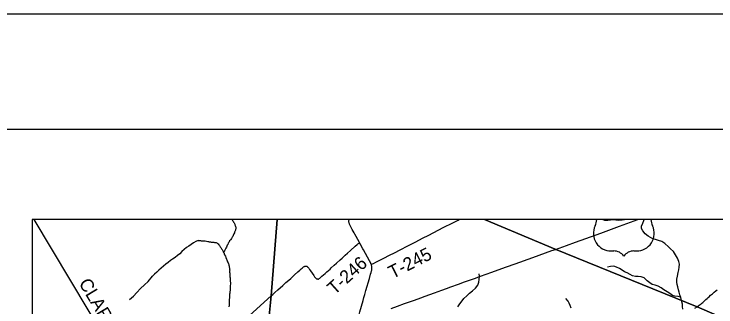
# Model space of a CAD drawing. Extents: x 0 to 34, y 0 to 22.
# Drawn here: x 17.083 to 20.142, y 20.726 to 22 of the extents above; entities that cross this region are included whole.
import ezdxf

# ---------------------------------------------------------------- set-up
doc = ezdxf.new("R2010")
doc.units = 0
for name, color, linetype in [('GM_X_Corporation', 7, 'Continuous'), ('GM_X_County_Road', 7, 'Continuous'), ('GM_X_County_Road_Text', 7, 'Continuous'), ('GM_X_Interstate_Shield', 7, 'Continuous'), ('GM_X_Minor_River', 7, 'Continuous'), ('GM_X_State_Route', 7, 'Continuous'), ('GM_X_Township_Road', 7, 'Continuous'), ('GM_X_Township_Road_Text', 7, 'Continuous'), ('GM_X_US_Location', 7, 'Continuous'), ('GM_X_US_Route', 7, 'Continuous'), ('SH_Border', 7, 'Continuous'), ('SH_Cut_Line', 7, 'Continuous')]:
    doc.layers.add(name, color=color, linetype=linetype)

msp = doc.modelspace()

# ---------------------------------------------------------------- linework, layer by layer
at = {"layer": 'GM_X_Corporation'}
for points in [[(18.23, 21.1059), (17.1625, 21.1059), (17.1625, 14.3059), (17.597, 14.3059), (17.6136, 14.4601), (17.7239, 15.6245), (17.7373, 15.7617), (17.7834, 16.317), (17.8718, 17.2256), (17.9672, 18.2605), (18.0387, 19.0962), (18.0879, 19.5959), (18.1731, 20.4696), (18.203, 20.7746)], [(18.23, 21.1059), (17.1625, 21.1059), (17.1625, 16.0215), (17.412, 16.1394), (17.7834, 16.317), (17.8718, 17.2256), (17.9672, 18.2605), (18.0387, 19.0962), (18.0879, 19.5959), (18.1731, 20.4696), (18.203, 20.7746)], [(17.597, 14.3059), (23.9625, 14.3059), (23.9625, 21.1059), (18.23, 21.1059), (18.203, 20.7746), (18.1731, 20.4696), (18.0879, 19.5959), (18.0387, 19.0962), (17.9672, 18.2605), (17.8718, 17.2256), (17.7834, 16.317), (17.7373, 15.7617), (17.7239, 15.6245), (17.6136, 14.4601)], [(23.8219, 21.1059), (19.1325, 21.1059), (19.4417, 20.9771), (20.0591, 20.7271), (20.5209, 20.5272), (20.9887, 20.3291), (21.1503, 20.1924), (21.2024, 20.1483), (21.462, 19.9289), (21.6862, 19.7442), (22.4736, 19.0897), (22.5453, 19.0171), (22.8523, 19.0143), (22.8728, 18.8666), (23.8372, 18.7818), (23.8567, 18.7798), (23.8401, 19.9225), (23.83, 20.7057)]]:
    msp.add_lwpolyline(points, close=True, dxfattribs=at)
msp.add_lwpolyline([(22.4736, 19.0897), (21.6862, 19.7442), (21.462, 19.9289), (21.2024, 20.1483), (21.1503, 20.1924), (20.9887, 20.3291), (20.5209, 20.5272), (20.0591, 20.7271), (19.4417, 20.9771), (19.1325, 21.1059), (18.23, 21.1059), (18.203, 20.7746), (18.1731, 20.4696), (18.0879, 19.5959), (18.0387, 19.0962), (17.9672, 18.2605), (17.8718, 17.2256), (17.7834, 16.317)], dxfattribs=at)
at = {"layer": 'GM_X_County_Road'}
for points in [[(17.7394, 20.168), (17.6942, 20.2387), (17.6421, 20.3201), (17.1708, 21.1059)], [(18.5889, 21.0055), (18.5868, 21.0092), (18.5809, 21.0199), (18.5738, 21.0327), (18.5684, 21.0424), (18.5652, 21.0481), (18.557, 21.0629), (18.5491, 21.0771), (18.546, 21.0834), (18.5451, 21.0854), (18.5443, 21.0873), (18.5435, 21.09), (18.5429, 21.0923), (18.5424, 21.0946), (18.5422, 21.0969), (18.5423, 21.0988), (18.5425, 21.1017), (18.5431, 21.1045), (18.5435, 21.1059)], [(18.6398, 20.9111), (18.6384, 20.9143), (18.6371, 20.9169), (18.6324, 20.9264), (18.6064, 20.9742), (18.6036, 20.9793), (18.5913, 21.0012), (18.5889, 21.0055)], [(18.5798, 20.665), (18.5829, 20.6767), (18.5834, 20.679), (18.584, 20.6813), (18.5903, 20.7053), (18.6038, 20.7535), (18.6078, 20.7675), (18.6113, 20.7799), (18.6163, 20.797), (18.6315, 20.8499), (18.6368, 20.8685), (18.6388, 20.8756), (18.6405, 20.8824), (18.6415, 20.8864), (18.6422, 20.8899), (18.6425, 20.8931), (18.6427, 20.8959), (18.6426, 20.8981), (18.6424, 20.9009), (18.6419, 20.9039), (18.6413, 20.9067), (18.6405, 20.9092), (18.6398, 20.9111)], [(20.0594, 20.7266), (20.0625, 20.7289), (20.066, 20.7314), (20.0689, 20.7336), (20.0724, 20.7363), (20.0767, 20.7397), (20.0803, 20.7426), (20.0844, 20.746), (20.0876, 20.7489), (20.0931, 20.7539), (20.0976, 20.7579), (20.1026, 20.7625), (20.1071, 20.7665), (20.1117, 20.7707), (20.1184, 20.7766), (20.1264, 20.7836), (20.1337, 20.79), (20.1413, 20.7967), (20.1463, 20.8011)], [(20.0501, 20.7206), (20.0594, 20.7266)]]:
    msp.add_lwpolyline(points, dxfattribs=at)
at = {"layer": 'GM_X_Interstate_Shield'}
for p, q in [((19.8583, 21.1059), (19.622, 21.1059)), ((19.6852, 20.9695), (19.6962, 20.9695)), ((19.7841, 20.9695), (19.7951, 20.9695))]:
    msp.add_line(p, q, dxfattribs=at)
for centre, radius, start, end in [((19.5453, 21.1121), 0.0769, 334.5471, 355.3305), ((19.935, 21.1121), 0.0769, 184.6695, 205.4529), ((19.6844, 21.0464), 0.0769, 154.8319, 270.6383), ((19.7959, 21.0464), 0.0769, 269.3617, 25.1681), ((19.6962, 20.9145), 0.0549, 36.8699, 90), ((19.7841, 20.9145), 0.0549, 90, 143.1301)]:
    msp.add_arc(centre, radius, start, end, dxfattribs=at)
at = {"layer": 'GM_X_Minor_River'}
for points in [[(18.0336, 21.1059), (18.0342, 21.105), (18.0357, 21.1023), (18.0383, 21.0985), (18.0394, 21.0954), (18.0423, 21.092), (18.0438, 21.0889), (18.0449, 21.0862), (18.0456, 21.0836), (18.0471, 21.0801), (18.0482, 21.0763), (18.0493, 21.0725), (18.0496, 21.0695), (18.0496, 21.0664), (18.0488, 21.0634), (18.048, 21.0604), (18.0468, 21.0577), (18.0452, 21.0539), (18.0444, 21.0509), (18.0433, 21.0483), (18.0409, 21.0445), (18.0397, 21.0415), (18.0374, 21.0366), (18.0358, 21.0328), (18.0339, 21.029), (18.0323, 21.0264), (18.0308, 21.0238), (18.0284, 21.02), (18.0257, 21.017), (18.0226, 21.0129), (18.0207, 21.0095), (18.0195, 21.0068), (18.0168, 21.0027), (18.0145, 20.9978), (18.0125, 20.994), (18.0109, 20.991), (18.009, 20.9865), (18.0063, 20.9816), (18.0047, 20.9786), (18.0031, 20.9759), (18.0016, 20.9725), (18.0004, 20.9695), (17.9988, 20.9657), (17.9961, 20.9635)], [(19.7504, 21.1059), (19.7425, 21.1045), (19.733, 21.1031), (19.7174, 21.1027), (19.7046, 21.1041), (19.6921, 21.1051), (19.6818, 21.1041), (19.6704, 21.1021), (19.6568, 21.1023), (19.6469, 21.1059)], [(19.9971, 20.7169), (19.9958, 20.7279), (19.9957, 20.7386), (19.9918, 20.7534), (19.9883, 20.7672), (19.9847, 20.7786), (19.9812, 20.7897), (19.9784, 20.8008), (19.9756, 20.8133), (19.9724, 20.8236), (19.9707, 20.8343), (19.9717, 20.8468), (19.9739, 20.8604), (19.9776, 20.8751), (19.9805, 20.8869), (19.9819, 20.8997), (19.9822, 20.9122), (19.9794, 20.9241), (19.9743, 20.9382), (19.9655, 20.952), (19.9571, 20.9666), (19.9437, 20.9783), (19.9348, 20.9879), (19.9188, 21.0023), (19.9057, 21.0113), (19.8911, 21.0157), (19.8775, 21.0191), (19.8666, 21.0223), (19.8561, 21.0282), (19.846, 21.0333), (19.8333, 21.0442), (19.8226, 21.0573), (19.8175, 21.0669), (19.8177, 21.0768), (19.8232, 21.09), (19.828, 21.1024), (19.8288, 21.1059)], [(17.8837, 21.015), (17.8854, 21.0145), (17.8758, 21.0101), (17.8655, 21.005), (17.8555, 20.998), (17.8447, 20.991), (17.8351, 20.984), (17.8247, 20.9759), (17.8147, 20.967), (17.805, 20.9573), (17.795, 20.9491), (17.7854, 20.9414), (17.7742, 20.9332), (17.7646, 20.9274), (17.755, 20.92), (17.745, 20.9126), (17.7342, 20.9033), (17.7246, 20.8948), (17.7145, 20.8863), (17.7049, 20.8774), (17.6952, 20.8685), (17.6863, 20.8603)], [(17.8837, 21.015), (17.886, 21.0148), (17.889, 21.0144), (17.8936, 21.0143), (17.8962, 21.0143), (17.8992, 21.0138), (17.9027, 21.0138), (17.9068, 21.0137), (17.911, 21.0133), (17.9137, 21.0133), (17.9163, 21.0132), (17.9212, 21.0124), (17.9277, 21.0112), (17.9311, 21.0104), (17.9337, 21.0099), (17.9364, 21.0095), (17.939, 21.0091), (17.9417, 21.0083), (17.9443, 21.0083), (17.9478, 21.0078), (17.9531, 21.0074), (17.9565, 21.007), (17.9591, 21.0065), (17.9633, 21.0057), (17.9667, 21.0045), (17.9697, 21.0026), (17.9727, 21.0003), (17.9749, 20.9964), (17.9783, 20.9934), (17.982, 20.988), (17.9843, 20.9842), (17.9857, 20.9815), (17.9876, 20.9784), (17.9895, 20.9757), (17.9913, 20.9723), (17.9928, 20.9696), (17.995, 20.9665), (17.9961, 20.9635), (17.9984, 20.96), (17.9994, 20.957), (18.0009, 20.9532), (18.0042, 20.9467), (18.0061, 20.9417), (18.009, 20.9344), (18.0101, 20.931), (18.0119, 20.926), (18.0138, 20.9218), (18.0164, 20.9172), (18.0171, 20.9142), (18.0185, 20.9108), (18.0189, 20.9081)], [(18.0189, 20.9081), (18.0203, 20.9031), (18.021, 20.8986), (18.0218, 20.8959), (18.0221, 20.8932), (18.0221, 20.8906), (18.0228, 20.8864), (18.0227, 20.8837), (18.0227, 20.8807), (18.0226, 20.8773), (18.023, 20.8731), (18.0229, 20.8693), (18.0232, 20.8606), (18.0235, 20.8575), (18.0246, 20.8533), (18.0252, 20.8453), (18.0252, 20.8427), (18.0255, 20.8385), (18.0258, 20.8313), (18.0261, 20.8252), (18.0256, 20.8187), (18.0256, 20.8149), (18.0255, 20.8112), (18.0254, 20.8058), (18.025, 20.8017), (18.0242, 20.7967), (18.0237, 20.7929), (18.0233, 20.7899), (18.0229, 20.7854), (18.0224, 20.7812), (18.022, 20.7763), (18.0219, 20.7706), (18.0214, 20.7656), (18.0214, 20.7626), (18.021, 20.7596), (18.0209, 20.7561), (18.0209, 20.7531), (18.0209, 20.7505), (18.0208, 20.7478), (18.0208, 20.7451), (18.0204, 20.7421), (18.0203, 20.7391), (18.0203, 20.7353), (18.0202, 20.7315), (18.0198, 20.7284), (18.0197, 20.7258)], [(19.9876, 20.7692), (19.9766, 20.7708), (19.9626, 20.7726), (19.9529, 20.7762), (19.9409, 20.784), (19.9289, 20.7922), (19.9147, 20.8009), (19.9028, 20.8091), (19.8904, 20.8158), (19.8769, 20.8213), (19.8637, 20.8243), (19.854, 20.8309), (19.8424, 20.8399), (19.8286, 20.8519), (19.8151, 20.8575), (19.8019, 20.8581), (19.7913, 20.8583), (19.7784, 20.8609), (19.7683, 20.8671), (19.7552, 20.8746), (19.7436, 20.8794), (19.7335, 20.8857), (19.7211, 20.8931), (19.708, 20.8994), (19.6971, 20.9034), (19.6827, 20.9022), (19.6697, 20.8991)], [(17.5866, 20.7577), (17.6033, 20.773), (17.6189, 20.7895), (17.6342, 20.8063), (17.6513, 20.822), (17.6677, 20.8369), (17.6863, 20.8603)], [(19.1085, 20.8338), (19.1102, 20.8448), (19.1109, 20.8592), (19.1096, 20.8706)], [(19.0169, 20.726), (19.0255, 20.7395), (19.036, 20.7522), (19.0434, 20.7626), (19.0561, 20.7749), (19.0681, 20.7857), (19.0808, 20.7957), (19.0943, 20.8079), (19.1036, 20.8203), (19.1085, 20.8338)], [(19.5111, 20.7208), (19.5064, 20.7319), (19.5025, 20.7418), (19.4981, 20.7518), (19.4874, 20.7634)]]:
    msp.add_lwpolyline(points, dxfattribs=at)
at = {"layer": 'GM_X_State_Route'}
for points in [[(19.442, 20.9765), (19.4901, 20.9938), (19.5293, 21.0078), (19.5743, 21.0241), (19.6398, 21.0476), (19.721, 21.077), (19.8009, 21.1059)], [(18.726, 20.7196), (18.7546, 20.7299), (18.7844, 20.7406), (18.8275, 20.756), (18.8552, 20.7659), (18.8749, 20.773), (18.9147, 20.7873), (18.9478, 20.7993), (18.9674, 20.8063), (18.9868, 20.8132), (19.0191, 20.8248), (19.0466, 20.8346), (19.0891, 20.85), (19.1161, 20.8598), (19.1649, 20.8772), (19.2088, 20.8929), (19.2296, 20.9003), (19.2667, 20.9137), (19.3433, 20.9412), (19.4264, 20.971), (19.442, 20.9765)]]:
    msp.add_lwpolyline(points, dxfattribs=at)
at = {"layer": 'GM_X_Township_Road'}
for points in [[(18.6398, 20.9111), (18.6439, 20.9131), (18.6488, 20.9155), (18.6593, 20.9207), (18.6738, 20.9282), (18.6919, 20.9374), (18.7224, 20.9526), (18.7373, 20.9604), (18.7689, 20.9765), (18.7955, 20.99), (18.8194, 21.0021), (18.834, 21.0096), (18.8632, 21.0245), (18.891, 21.0388), (18.931, 21.0594), (18.9563, 21.0724), (18.9924, 21.0907), (19.0177, 21.1035), (19.0224, 21.1059)], [(18.2032, 20.774), (18.2103, 20.7803), (18.2198, 20.7888), (18.2327, 20.8003), (18.2548, 20.8199), (18.268, 20.8316), (18.2803, 20.8425), (18.2892, 20.8504), (18.2954, 20.856), (18.3052, 20.865), (18.3202, 20.8785), (18.3286, 20.8861), (18.3343, 20.8912), (18.3385, 20.895), (18.343, 20.8989), (18.345, 20.9004), (18.3468, 20.9016), (18.3484, 20.9024), (18.3504, 20.9031), (18.3518, 20.9035), (18.3538, 20.9037), (18.3554, 20.9036), (18.3568, 20.9034), (18.3583, 20.9029), (18.3597, 20.9021), (18.3611, 20.9011), (18.3628, 20.8997), (18.3648, 20.8975), (18.367, 20.8948), (18.3708, 20.8895), (18.3755, 20.8826), (18.3888, 20.8629), (18.3929, 20.8571), (18.3951, 20.8541), (18.3976, 20.8514), (18.3997, 20.8497), (18.4012, 20.8488), (18.4031, 20.848), (18.4048, 20.8476), (18.4064, 20.8473), (18.4078, 20.8473), (18.4091, 20.8475), (18.4114, 20.8482), (18.4133, 20.8495), (18.4156, 20.8512), (18.4176, 20.8528), (18.425, 20.8594), (18.4316, 20.8655), (18.4385, 20.8717), (18.4458, 20.8783), (18.4528, 20.8846), (18.4599, 20.891), (18.4653, 20.896), (18.4775, 20.907), (18.4884, 20.917), (18.5035, 20.9305), (18.5125, 20.9386), (18.5259, 20.9507), (18.5361, 20.9599), (18.549, 20.9716), (18.5699, 20.9904), (18.5778, 20.9973), (18.5808, 21), (18.5839, 21.0023), (18.5868, 21.0041), (18.5889, 21.0055)], [(17.6421, 20.3201), (17.8646, 20.4744), (17.9052, 20.5041), (17.9659, 20.5583), (18.2032, 20.774)]]:
    msp.add_lwpolyline(points, dxfattribs=at)
at = {"layer": 'GM_X_US_Route'}
for points in [[(19.442, 20.9765), (19.4901, 20.9938), (19.5293, 21.0078), (19.5743, 21.0241), (19.6398, 21.0476), (19.721, 21.077), (19.8009, 21.1059)], [(18.726, 20.7196), (18.7546, 20.7299), (18.7844, 20.7406), (18.8275, 20.756), (18.8552, 20.7659), (18.8749, 20.773), (18.9147, 20.7873), (18.9478, 20.7993), (18.9674, 20.8063), (18.9868, 20.8132), (19.0191, 20.8248), (19.0466, 20.8346), (19.0891, 20.85), (19.1161, 20.8598), (19.1649, 20.8772), (19.2088, 20.8929), (19.2296, 20.9003), (19.2667, 20.9137), (19.3433, 20.9412), (19.4264, 20.971), (19.442, 20.9765)]]:
    msp.add_lwpolyline(points, dxfattribs=at)
at = {"layer": 'SH_Border'}
msp.add_lwpolyline([(1.5, 21.5), (33.5, 21.5), (33.5, 0.5), (1.5, 0.5)], close=True, dxfattribs=at)
at = {"layer": 'SH_Cut_Line'}
msp.add_lwpolyline([(0, 0), (34, 0), (34, 22), (0, 22)], close=True, dxfattribs=at)

# ---------------------------------------------------------------- texts
at = {"layer": 'GM_X_County_Road_Text'}
msp.add_text('CLARKSVILLE', height=0.056818, rotation=300.9813, dxfattribs=at).set_placement((17.3634, 20.8296))
at = {"layer": 'GM_X_Township_Road_Text'}
for s, rotation, p in [('T-245', 27.0744, (18.7323, 20.8472)), ('T-246', 42.0493, (18.4795, 20.776))]:
    msp.add_text(s, height=0.05682, rotation=rotation, dxfattribs=at).set_placement(p)
at = {"layer": 'GM_X_US_Location'}
for s in ['0', '/']:
    msp.add_text(s, height=0.000189, dxfattribs=at).set_placement((19.7401, 21.0838))
msp.add_text('22', height=0.000189, rotation=0, dxfattribs=at).set_placement((19.701, 21.0446))

doc.saveas('drawing.dxf')
